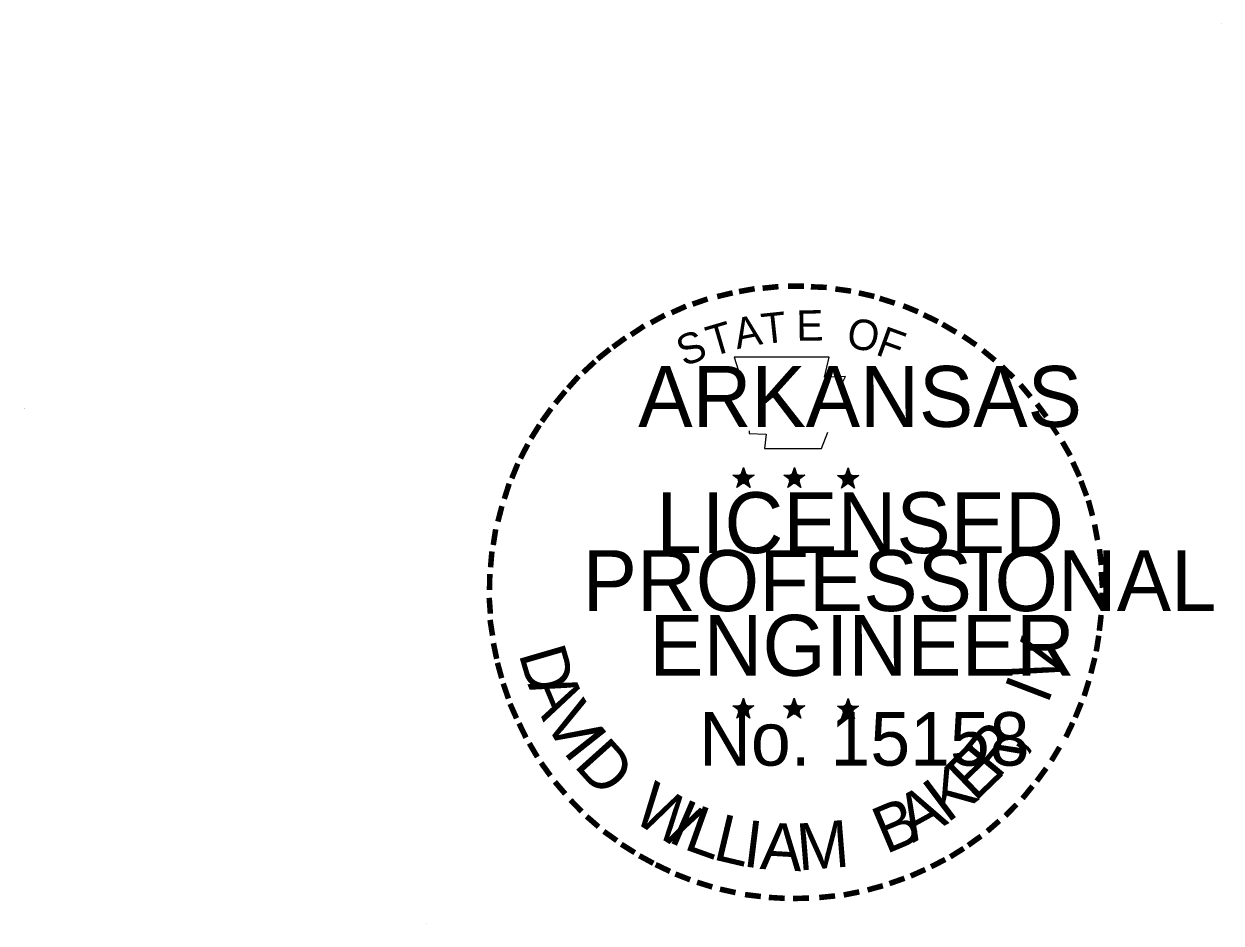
# Model space of a CAD drawing. Extents: x 1416408 to 1429341, y 372694 to 383211.
# Drawn here: x 1418872.4 to 1419201.4, y 381820.9 to 382068.2 of the extents above; entities that cross this region are included whole.
import ezdxf

# ---------------------------------------------------------------- set-up
doc = ezdxf.new("R2010")
doc.units = 0
for name, color, linetype in [('R_Border', 7, 'Continuous'), ('R_Border PE', 7, 'Continuous'), ('R_Border Prem', 7, 'Continuous'), ('R_No Plot', 7, 'Continuous')]:
    doc.layers.add(name, color=color, linetype=linetype)

msp = doc.modelspace()

# ---------------------------------------------------------------- linework, layer by layer
at = {"layer": 'R_Border'}
msp.add_line((1419201.41, 382068.17), (1419201.41, 382068.17), dxfattribs=at)
at = {"layer": 'R_Border PE'}
for p, q in [((1419067.23, 381944.05), (1419070.15, 381943.12)), ((1419067.23, 381944.05), (1419069.35, 381943.68)), ((1419067.23, 381944.05), (1419069.22, 381943.03)), ((1419068.35, 381940.64), (1419070.15, 381943.12)), ((1419070.15, 381946.18), (1419069.81, 381944.07)), ((1419070.15, 381943.12), (1419070.15, 381946.18)), ((1419070.15, 381946.18), (1419070.56, 381944.09)), ((1419073.06, 381944.05), (1419070.15, 381943.12)), ((1419071.94, 381940.64), (1419070.15, 381943.12)), ((1419073.06, 381944.05), (1419070.66, 381943.64)), ((1419071.94, 381940.64), (1419070.79, 381943.07)), ((1419073.06, 381944.05), (1419071.35, 381943.2)), ((1419081.21, 381944.05), (1419084.14, 381943.12)), ((1419081.21, 381944.05), (1419083.33, 381943.68)), ((1419081.21, 381944.05), (1419083.2, 381943.03)), ((1419082.33, 381940.64), (1419084.14, 381943.12)), ((1419084.14, 381946.18), (1419083.79, 381944.07)), ((1419084.14, 381943.12), (1419084.14, 381946.18)), ((1419084.14, 381946.18), (1419084.55, 381944.09)), ((1419087.04, 381944.05), (1419084.14, 381943.12)), ((1419085.92, 381940.64), (1419084.14, 381943.12)), ((1419087.04, 381944.05), (1419084.65, 381943.64)), ((1419085.92, 381940.64), (1419084.77, 381943.07)), ((1419087.04, 381944.05), (1419085.33, 381943.2)), ((1419095.98, 381943.95), (1419098.9, 381943.02)), ((1419095.98, 381943.95), (1419098.1, 381943.58)), ((1419095.98, 381943.95), (1419097.97, 381942.93)), ((1419097.1, 381940.54), (1419098.9, 381943.02)), ((1419098.9, 381946.08), (1419098.56, 381943.97)), ((1419098.9, 381943.02), (1419098.9, 381946.08)), ((1419098.9, 381946.08), (1419099.31, 381943.99)), ((1419101.81, 381943.95), (1419098.9, 381943.02)), ((1419100.69, 381940.54), (1419098.9, 381943.02)), ((1419101.81, 381943.95), (1419099.41, 381943.54)), ((1419100.69, 381940.54), (1419099.54, 381942.97)), ((1419101.81, 381943.95), (1419100.1, 381943.1)), ((1419068.35, 381940.64), (1419069.4, 381942.68)), ((1419068.35, 381940.64), (1419070.14, 381942.45)), ((1419071.94, 381940.64), (1419070.14, 381942.43)), ((1419082.33, 381940.64), (1419083.38, 381942.68)), ((1419082.33, 381940.64), (1419084.12, 381942.45)), ((1419085.92, 381940.64), (1419084.12, 381942.43)), ((1419097.1, 381940.54), (1419098.15, 381942.58)), ((1419097.1, 381940.54), (1419098.89, 381942.35)), ((1419100.69, 381940.54), (1419098.89, 381942.33)), ((1419067.2, 381880.65), (1419070.12, 381879.72)), ((1419067.2, 381880.65), (1419069.32, 381880.27)), ((1419067.2, 381880.65), (1419069.18, 381879.63)), ((1419070.12, 381882.78), (1419069.78, 381880.67)), ((1419070.12, 381879.72), (1419070.12, 381882.78)), ((1419070.12, 381882.78), (1419070.53, 381880.68)), ((1419073.03, 381880.65), (1419070.12, 381879.72)), ((1419073.03, 381880.65), (1419070.63, 381880.24)), ((1419073.03, 381880.65), (1419071.32, 381879.8)), ((1419081.17, 381880.65), (1419084.09, 381879.72)), ((1419081.17, 381880.65), (1419083.29, 381880.27)), ((1419081.17, 381880.65), (1419083.16, 381879.63)), ((1419084.09, 381882.78), (1419083.75, 381880.67)), ((1419084.09, 381879.72), (1419084.09, 381882.78)), ((1419084.09, 381882.78), (1419084.5, 381880.68)), ((1419087, 381880.65), (1419084.09, 381879.72)), ((1419087, 381880.65), (1419084.6, 381880.24)), ((1419087, 381880.65), (1419085.29, 381879.8)), ((1419095.97, 381880.57), (1419098.89, 381879.64)), ((1419095.97, 381880.57), (1419098.08, 381880.19)), ((1419095.97, 381880.57), (1419097.95, 381879.55)), ((1419098.89, 381882.69), (1419098.54, 381880.58)), ((1419098.89, 381879.64), (1419098.89, 381882.69)), ((1419098.89, 381882.69), (1419099.3, 381880.6)), ((1419101.79, 381880.57), (1419098.89, 381879.64)), ((1419101.79, 381880.57), (1419099.4, 381880.16)), ((1419101.79, 381880.57), (1419100.08, 381879.71)), ((1419068.31, 381877.24), (1419070.12, 381879.72)), ((1419068.31, 381877.24), (1419069.37, 381879.28)), ((1419068.31, 381877.24), (1419070.1, 381879.05)), ((1419071.9, 381877.24), (1419070.1, 381879.03)), ((1419071.9, 381877.24), (1419070.12, 381879.72)), ((1419071.9, 381877.24), (1419070.76, 381879.67)), ((1419082.29, 381877.24), (1419084.09, 381879.72)), ((1419082.29, 381877.24), (1419083.34, 381879.28)), ((1419082.29, 381877.24), (1419084.08, 381879.05)), ((1419085.88, 381877.24), (1419084.08, 381879.03)), ((1419085.88, 381877.24), (1419084.09, 381879.72)), ((1419085.88, 381877.24), (1419084.73, 381879.67)), ((1419097.08, 381877.15), (1419098.89, 381879.64)), ((1419097.08, 381877.15), (1419098.13, 381879.19)), ((1419097.08, 381877.15), (1419098.87, 381878.97)), ((1419100.67, 381877.15), (1419098.87, 381878.94)), ((1419100.67, 381877.15), (1419098.89, 381879.64)), ((1419100.67, 381877.15), (1419099.52, 381879.59))]:
    msp.add_line(p, q, dxfattribs=at)
for points in [[(1419067.58, 381976.52), (1419069.83, 381969.6)], [(1419096.97, 381968.8), (1419098.16, 381971.18), (1419092.42, 381970.98), (1419093.66, 381976.52), (1419067.58, 381976.52)], [(1419071.69, 381956.23), (1419071.69, 381955.51), (1419076.41, 381955.35), (1419075.96, 381951.39), (1419091.61, 381951.39), (1419093.29, 381955.87)], [(1419070.15, 381946.18), (1419071.94, 381940.64), (1419067.23, 381944.05), (1419073.06, 381944.05), (1419068.35, 381940.64), (1419070.15, 381946.18)], [(1419084.14, 381946.18), (1419085.92, 381940.64), (1419081.21, 381944.05), (1419087.04, 381944.05), (1419082.33, 381940.64), (1419084.14, 381946.18)], [(1419098.9, 381946.08), (1419100.69, 381940.54), (1419095.98, 381943.95), (1419101.81, 381943.95), (1419097.1, 381940.54), (1419098.9, 381946.08)], [(1419070.12, 381882.78), (1419071.9, 381877.24), (1419067.2, 381880.65), (1419073.03, 381880.65), (1419068.31, 381877.24), (1419070.12, 381882.78)], [(1419084.09, 381882.78), (1419085.88, 381877.24), (1419081.17, 381880.65), (1419087, 381880.65), (1419082.29, 381877.24), (1419084.09, 381882.78)], [(1419098.89, 381882.69), (1419100.67, 381877.15), (1419095.97, 381880.57), (1419101.79, 381880.57), (1419097.08, 381877.15), (1419098.89, 381882.69)]]:
    msp.add_lwpolyline(points, dxfattribs=at)
for centre, radius in [((1419070.15, 381943.12), 1.44), ((1419070.15, 381943.12), 1.21), ((1419070.15, 381943.12), 0.969), ((1419070.15, 381943.12), 0.83), ((1419070.15, 381943.12), 0.626), ((1419070.15, 381943.12), 0.415), ((1419070.15, 381943.12), 0.248), ((1419084.13, 381943.12), 1.44), ((1419084.13, 381943.12), 1.21), ((1419084.13, 381943.12), 0.969), ((1419084.13, 381943.12), 0.83), ((1419084.13, 381943.12), 0.626), ((1419084.13, 381943.12), 0.415), ((1419084.13, 381943.12), 0.248), ((1419098.9, 381943.02), 1.44), ((1419098.9, 381943.02), 1.21), ((1419098.9, 381943.02), 0.969), ((1419098.9, 381943.02), 0.83), ((1419098.9, 381943.02), 0.626), ((1419098.9, 381943.02), 0.415), ((1419098.9, 381943.02), 0.248), ((1419070.11, 381879.71), 1.44), ((1419070.11, 381879.71), 1.21), ((1419070.11, 381879.71), 0.969), ((1419070.11, 381879.71), 0.83), ((1419084.09, 381879.71), 1.44), ((1419084.09, 381879.71), 1.21), ((1419084.09, 381879.71), 0.969), ((1419084.09, 381879.71), 0.83), ((1419098.88, 381879.63), 1.44), ((1419098.88, 381879.63), 1.21), ((1419098.88, 381879.63), 0.969), ((1419098.88, 381879.63), 0.83), ((1419070.11, 381879.71), 0.626), ((1419070.11, 381879.71), 0.415), ((1419070.11, 381879.71), 0.248), ((1419084.09, 381879.71), 0.626), ((1419084.09, 381879.71), 0.415), ((1419084.09, 381879.71), 0.248), ((1419098.88, 381879.63), 0.626), ((1419098.88, 381879.63), 0.415), ((1419098.88, 381879.63), 0.248)]:
    msp.add_circle(centre, radius, dxfattribs=at)
at = {"layer": 'R_No Plot'}
msp.add_line((1418983.09, 381820.89), (1418983.09, 381820.89), dxfattribs=at)

# ---------------------------------------------------------------- texts
at = {"layer": 'R_Border PE'}
for s, height, rotation, p in [('-', 13.4, 10.2193, (1419069.05, 381989.33)), ('-', 13.4, 5.8968, (1419075.15, 381990.25)), ('-', 13.4, 0.1862, (1419081.61, 381990.85)), ('-', 13.4, 357.743, (1419087.67, 381990.74)), ('-', 13.4, 352.1617, (1419093.9, 381990.27)), ('-', 13.4, 19.1761, (1419057.09, 381985.95)), ('-', 13.4, 13.6302, (1419063.37, 381987.97)), ('-', 13.4, 347.2049, (1419099.92, 381989.32)), ('-', 13.4, 342.3362, (1419105.23, 381988.02)), ('-', 13.4, 24.3072, (1419051.78, 381983.7)), ('T', 8.37, 6.0228, (1419075.48, 381980.09)), ('E', 8.37, 0.8323, (1419084.73, 381981.01)), ('-', 13.4, 337.8551, (1419111.38, 381986.16)), ('-', 13.4, 34.0636, (1419041.49, 381977.95)), ('-', 13.4, 28.7918, (1419046.48, 381981.05)), ('T', 8.37, 16.4036, (1419061.45, 381976.59)), ('A', 8.37, 11.2132, (1419068.37, 381978.7)), ('O', 8.37, 350.4515, (1419098.16, 381979.25)), ('-', 13.4, 334.1211, (1419116.67, 381983.89)), ('-', 13.4, 329.6409, (1419121.52, 381981.52)), ('-', 13.4, 36.2317, (1419036.65, 381974.64)), ('S', 8.37, 21.594, (1419053.8, 381973.82)), ('F', 8.37, 340.0707, (1419106.14, 381977.34)), ('-', 13.4, 325.8627, (1419126.9, 381978.5)), ('-', 13.4, 38.9507, (1419032.66, 381971.48)), ('-', 13.4, 42.9622, (1419029.04, 381967.99)), ('-', 13.4, 320.5297, (1419132.01, 381974.93)), ('-', 13.4, 315.5786, (1419137.02, 381970.84)), ('-', 13.4, 48.4231, (1419025.29, 381963.99)), ('-', 13.4, 309.8797, (1419141.78, 381966.24)), ('-', 13.4, 50.6142, (1419021.91, 381959.92)), ('-', 13.4, 54.2325, (1419018.46, 381955.17)), ('-', 13.4, 306.6522, (1419146.18, 381961.2)), ('-', 13.4, 58.0706, (1419015.73, 381950.76)), ('-', 11.72, 303.6753, (1419150.25, 381956.44)), ('-', 13.4, 62.8713, (1419013.11, 381945.62)), ('-', 13.4, 299.6684, (1419152.92, 381951.36)), ('-', 13.4, 67.7743, (1419010.95, 381940.5)), ('-', 13.4, 294.6628, (1419155.63, 381946.24)), ('-', 13.4, 72.3945, (1419009.11, 381935.23)), ('-', 13.4, 290.5728, (1419157.78, 381941.41)), ('-', 13.4, 285.1233, (1419159.74, 381936.55)), ('-', 13.4, 75.461, (1419007.46, 381929.25)), ('-', 13.4, 280.5493, (1419161.42, 381930.34)), ('-', 13.4, 81.2013, (1419006.36, 381923.28)), ('-', 13.4, 276.5962, (1419162.77, 381923.91)), ('-', 13.4, 85.1863, (1419005.72, 381917.5)), ('-', 13.4, 89.0622, (1419005.51, 381911.63)), ('-', 13.4, 274.3301, (1419163.27, 381917.86)), ('-', 13.4, 94.1959, (1419005.8, 381905.56)), ('-', 13.4, 269.9407, (1419163.56, 381912.57)), ('-', 13.4, 98.9479, (1419006.41, 381899.97)), ('-', 13.4, 263.5172, (1419163.4, 381907)), ('-', 13.4, 101.7149, (1419007.54, 381893.84)), ('D', 12.89, 286.2848, (1419008.28, 381894.99)), ('V', 12.89, 72.6573, (1419155.56, 381885.28)), ('-', 13.4, 260.9953, (1419162.81, 381901.52)), ('-', 13.4, 255.7626, (1419161.89, 381895.85)), ('-', 13.4, 105.4578, (1419008.89, 381888.86)), ('-', 13.4, 109.0874, (1419010.69, 381883.57)), ('A', 12.89, 292.7835, (1419010.73, 381886.61)), ('I', 12.89, 69.0301, (1419153.7, 381880.77)), ('-', 13.4, 252.8681, (1419160.37, 381889.82)), ('-', 13.4, 114.0643, (1419012.82, 381878.58)), ('V', 12.89, 300.7936, (1419015.03, 381876.73)), ('-', 13.4, 247.8887, (1419158.5, 381884.18)), ('-', 13.4, 115.7289, (1419015.37, 381873.41)), ('I', 12.89, 308.3502, (1419020.32, 381868.05)), ('R', 12.89, 50.3651, (1419139.89, 381859.93)), ('-', 13.4, 244.6197, (1419156.31, 381878.92)), ('-', 13.4, 120.4471, (1419018.36, 381868.5)), ('D', 12.89, 311.9774, (1419023.25, 381864.15)), (',', 12.89, 57.4684, (1419145.94, 381867.31)), ('E', 12.89, 44.0175, (1419133.74, 381854)), ('-', 13.4, 239.0712, (1419153.01, 381872.62)), ('-', 13.4, 125.8934, (1419021.74, 381863.81)), ('K', 12.89, 36.9143, (1419126.13, 381848.22)), ('-', 13.4, 233.8452, (1419149.65, 381867.16)), ('-', 13.4, 130.7181, (1419025.6, 381859.19)), ('W', 12.89, 328.0731, (1419038.98, 381849.37)), ('A', 12.89, 28.9042, (1419116.77, 381842.89)), ('-', 13.4, 231.2538, (1419146.05, 381862.42)), ('-', 13.4, 134.2238, (1419029.93, 381854.62)), ('I', 12.89, 336.6877, (1419048.92, 381843.43)), ('B', 12.89, 22.8589, (1419109.27, 381839.76)), ('-', 13.4, 138.9338, (1419034.33, 381850.74)), ('L', 12.89, 340.3149, (1419053.35, 381841.38)), ('-', 13.4, 225.7653, (1419142.04, 381857.69)), ('L', 12.89, 346.6625, (1419061.39, 381838.5)), ('I', 12.89, 353.0101, (1419069.69, 381836.52)), ('A', 12.89, 356.6373, (1419074.52, 381835.8)), ('M', 12.89, 4.6473, (1419085.28, 381835.31)), ('-', 13.4, 221.0851, (1419137.66, 381853.43)), ('-', 13.4, 144.6463, (1419038.98, 381847.34)), ('-', 13.4, 215.7363, (1419133.07, 381849.48)), ('-', 13.4, 148.0898, (1419043.68, 381844.23)), ('-', 13.4, 212.2491, (1419128.6, 381846.24)), ('-', 13.4, 151.5704, (1419048.53, 381841.51)), ('-', 13.4, 154.6002, (1419052.9, 381839.44)), ('-', 13.4, 207.3568, (1419123.93, 381843.35)), ('-', 13.4, 158.5612, (1419058.12, 381837.32)), ('-', 13.4, 204.2516, (1419118.7, 381840.67)), ('-', 13.4, 162.7983, (1419063.87, 381835.53)), ('-', 13.4, 195.4743, (1419107.85, 381836.36)), ('-', 13.4, 199.4643, (1419113.42, 381838.35)), ('-', 13.4, 167.5555, (1419069.86, 381834.16)), ('-', 13.4, 173.1155, (1419076.32, 381833.24)), ('-', 13.4, 176.5183, (1419082.59, 381832.8)), ('-', 13.4, 181.5918, (1419088.81, 381832.96)), ('-', 13.4, 185.8167, (1419095.59, 381833.59)), ('-', 13.4, 191.2858, (1419101.75, 381834.7))]:
    msp.add_text(s, height=height, rotation=rotation, dxfattribs=at).set_placement(p)
for s, height, p in [('ARKANSAS', 16.744, (1419041.23, 381957.36)), ('LICENSED', 16.744, (1419046.23, 381922.63)), ('PROFESSIONAL', 16.7441, (1419025.94, 381906.69)), ('ENGINEER', 16.744, (1419044.25, 381888.9)), ('No. 15158', 14.71, (1419057.99, 381864.19)), ('AAMU', 0.000167, (1419083.54, 381835.27))]:
    msp.add_text(s, height=height, dxfattribs=at).set_placement(p)
at = {"layer": 'R_Border Prem'}
msp.add_text('DWB', height=0.0837, dxfattribs=at).set_placement((1418872.37, 381962.28))

doc.saveas('drawing.dxf')
